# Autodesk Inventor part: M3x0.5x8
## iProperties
Company: 한국ATC센터
Created: 2009-02
Part Number: M3x0.5x8
Document SubType Name: Modeling
Designer: KYOUNG IL JANG
Density: 2.71 g/cm^3
Mass: 97.9591 g
Surface Area: 115.525 cm^2
Volume: 36.1473 cm^3
Material: 알루미늄-6061
Vendor: CBT Solutions
Author: KYOUNG IL JANG
